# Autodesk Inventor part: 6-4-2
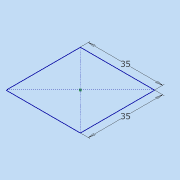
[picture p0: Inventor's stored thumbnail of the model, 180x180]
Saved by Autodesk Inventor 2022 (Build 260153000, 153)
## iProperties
Created: 2021-07
Part Number: 6-4-2
Material: 一般
Document SubType Name: Modeling
Designer: DesignLab
Density: 1 g/cm^3
Appearance: 既定
Author: DesignLab
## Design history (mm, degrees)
sketch "スケッチ1"
  geometry: L1 (-17.5, -17.5)-(17.5, -17.5); L2 (17.5, -17.5)-(17.5, 17.5); L3 (17.5, 17.5)-(-17.5, 17.5); L4 (-17.5, 17.5)-(-17.5, -17.5); L5 (-17.5, -17.5)-(17.5, 17.5); L6 (17.5, -17.5)-(-17.5, 17.5); 1 further point
  constraints: 12 end point, 2 midpoint, 2 parallel, 1 horizontal, 1 perpendicular
  dimensions: "d0" = 35 dimension on point (0, 0) L1.start L2.end L1.end L3.end L1 L2 L3 L4 L5 L6; "d0" = 35 distance of L3.end L2.end; "d1" = 35 distance of L2.end L1.end
